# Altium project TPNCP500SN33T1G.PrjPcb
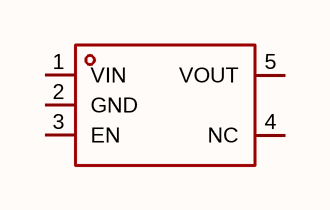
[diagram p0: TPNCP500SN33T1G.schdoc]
1 sheet, 1 parts. Net scope: global (net labels, ports and power ports of the same name join across sheets).

## Sheet TPNCP500SN33T1G.schdoc
size 127 x 101 mm

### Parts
U?  tpncp500sn33t1g  [SOT-23-5_L2.9-W1.6-P0.95-LS2.8-BR]  (value not drawn)

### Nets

Not connected (* = marked no-connect by the designer): U? 1(VIN) 2(GND) 3(EN) 4(NC) 5(VOUT)

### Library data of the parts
U? = tpncp500sn33t1g: 输出极性:正极;工作电压:5.5V;输出电压:3.3V;输出电流:600mA;电源纹波抑制比(PSRR):80dB@(100Hz);输出类型:固定;; Manufacturer: TECH PUBLIC(台舟); AddInBom: yes; ModelId: 7ba65df16e7b4570af156e925f9c37fe; ModelTransform: 114.173,114.173,0,90,0,0,0,0,0; Output Configuration: 正极; Voltage - Supply: 5.5V; Output Voltage: 3.3V; Output Current: 600mA; Voltage Dropout: 360mV@(600mA); standby current: 2uA; Noise: 50uVrms; Output Type: 固定; Number of Outputs: 1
